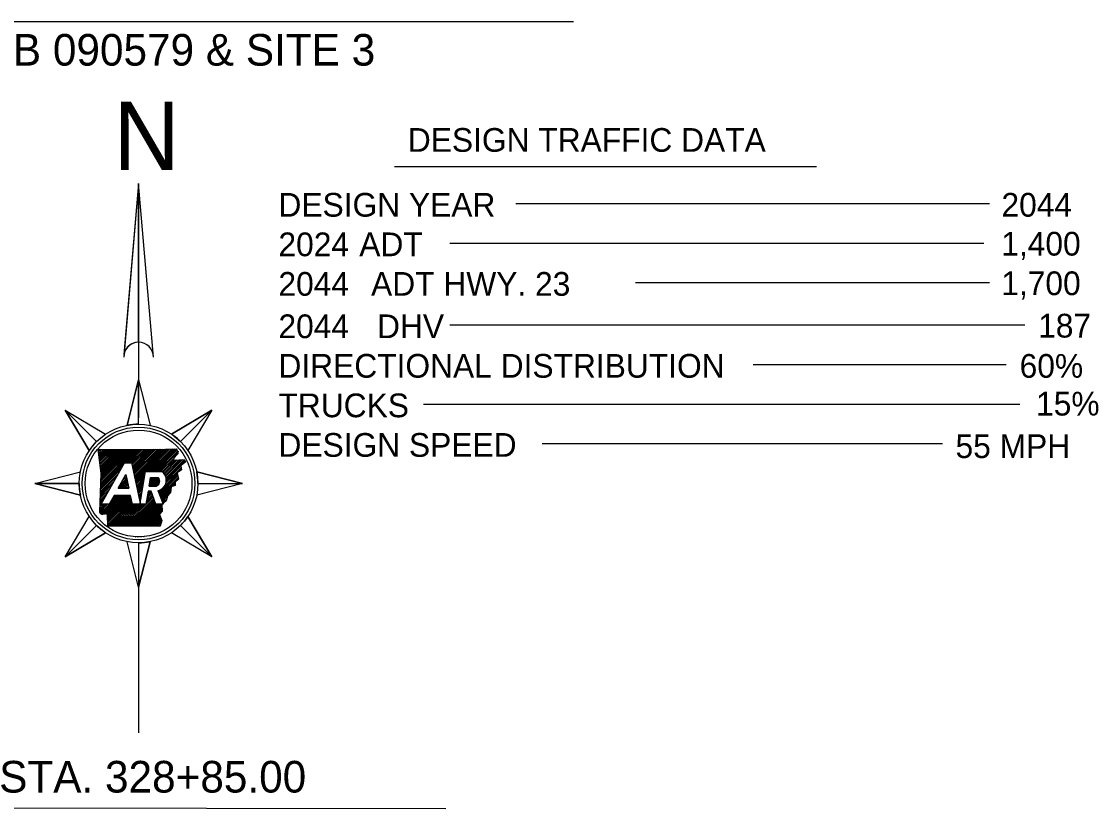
# Model space of a CAD drawing. Extents: x 0 to 3171, y 0 to 2059.
# Drawn here: x 2315 to 3132, y 658 to 1255 of the extents above; entities that cross this region are included whole.
import ezdxf

# ---------------------------------------------------------------- set-up
doc = ezdxf.new("R2010")
doc.units = 0
for name, color, linetype in [('Default', 7, 'Continuous'), ('R_Draft', 7, 'Continuous'), ('R_Water Annot', 7, 'Continuous')]:
    doc.layers.add(name, color=color, linetype=linetype)

msp = doc.modelspace()

# ---------------------------------------------------------------- linework, layer by layer
at = {"layer": 'Default'}
for p, q in [((2172.54, 1255.37), (2733.73, 1255.37)), ((2598, 1145.44), (2918, 1145.44)), ((2690.1, 1117.32), (3049.37, 1117.32)), ((2640.1, 1087.32), (3044.92, 1087.32)), ((2780.81, 1057.32), (3049.37, 1057.32)), ((2640.1, 1025.15), (3076.05, 1025.15)), ((2870.1, 995.15), (3061.97, 995.15)), ((2620.1, 965.15), (3072.35, 965.15)), ((2710.1, 935.15), (3013.64, 935.15))]:
    msp.add_line(p, q, dxfattribs=at)
msp.add_lwpolyline([(1931.87, 1191.31), (2273.76, 658.86), (2637.04, 658.32)], dxfattribs=at)
at = {"layer": 'R_Draft'}
for p, q in [((2404.02, 1132.45), (2392.93, 1002.73)), ((2404.02, 1132.45), (2404.02, 954.79)), ((2404.02, 1012.07), (2404.02, 1132.45)), ((2393.08, 1004.54), (2393.59, 1005.04)), ((2393.14, 1005.24), (2394.17, 1006.26)), ((2404.02, 983.63), (2395.25, 949.02)), ((2404.02, 949.88), (2404.02, 983.63)), ((2348.33, 960.56), (2372.2, 936.7)), ((2372.2, 936.7), (2348.33, 960.56)), ((2348.33, 960.56), (2366.61, 929.89)), ((2459.7, 960.56), (2429.03, 942.29)), ((2435.83, 936.7), (2459.7, 960.56)), ((2435.83, 936.7), (2459.7, 960.56)), ((2375.6, 889.12), (2393.35, 920.47)), ((2393.35, 920.47), (2398.63, 920.47)), ((2388.66, 901.42), (2394.46, 911.68)), ((2409.34, 913.93), (2421.67, 913.93)), ((2413.18, 909.51), (2418.97, 909.51)), ((2482.77, 904.88), (2448.15, 913.64)), ((2325.27, 904.88), (2359.02, 904.88)), ((2359.02, 904.88), (2325.27, 904.88)), ((2325.27, 904.88), (2359.88, 896.12)), ((2388.66, 901.42), (2396.66, 901.42)), ((2413.5, 899.09), (2411.36, 899.09)), ((2412.01, 902.81), (2417.3, 902.81)), ((2417.18, 889.12), (2413.5, 899.09)), ((2418.72, 899.62), (2422.6, 889.12)), ((2449.02, 904.88), (2482.77, 904.88)), ((2449.02, 904.88), (2482.77, 904.88)), ((2385.41, 895.7), (2381.69, 889.12)), ((2397.88, 895.7), (2385.41, 895.7)), ((2381.69, 889.12), (2375.6, 889.12)), ((2409.63, 889.12), (2399.29, 889.12)), ((2422.6, 889.12), (2417.18, 889.12)), ((2459.7, 849.2), (2441.42, 879.87)), ((2348.33, 849.2), (2372.2, 873.06)), ((2372.2, 873.06), (2348.33, 849.2)), ((2348.33, 849.2), (2379, 867.47)), ((2435.83, 873.06), (2459.7, 849.2)), ((2435.83, 873.06), (2459.7, 849.2)), ((2404.01, 859.88), (2404.02, 859.88)), ((2404.02, 826.13), (2412.78, 860.74)), ((2404.02, 859.88), (2404.02, 715.83)), ((2404.02, 859.88), (2404.02, 826.13))]:
    msp.add_line(p, q, dxfattribs=at)
for points in [[(2415.27, 1000.82), (2404.02, 1132.45), (2392.77, 1000.82)], [(2395.25, 949.02), (2404.02, 983.63), (2412.78, 949.02)], [(2366.61, 929.89), (2348.33, 960.56), (2379, 942.29)], [(2429.03, 942.29), (2459.7, 960.56), (2441.42, 929.89)], [(2373.29, 930.64), (2390.85, 930.63), (2406.26, 930.66), (2424.44, 930.94), (2432.87, 931.14)], [(2374.56, 883.13), (2375.54, 912.59), (2373.29, 930.64)], [(2438.38, 923.07), (2439.9, 921.48), (2436.11, 918.37), (2436.52, 915.23), (2433.27, 913.08), (2434.39, 908.25), (2431.88, 905.97), (2431.66, 903.48), (2428.61, 902.38), (2428.14, 897.7), (2425.95, 895.36), (2424.89, 891.83), (2421.71, 888.91), (2421.95, 883.76), (2419.78, 881.34), (2421.76, 876.92), (2420.39, 872.53)], [(2430.26, 922.66), (2438.5, 923.08)], [(2398.63, 920.47), (2405.16, 889.95), (2409.34, 913.93)], [(2359.88, 896.12), (2325.27, 904.88), (2359.88, 913.64)], [(2394.46, 911.68), (2396.66, 901.42)], [(2412.01, 902.81), (2413.18, 909.51)], [(2448.15, 913.64), (2482.77, 904.88), (2448.15, 896.12)], [(2411.36, 899.09), (2409.63, 889.12)], [(2399.29, 889.12), (2397.88, 895.7)], [(2379, 867.47), (2348.33, 849.2), (2366.61, 879.87)], [(2420.39, 872.53), (2380.59, 872.6), (2380.57, 881.38)], [(2441.42, 879.87), (2459.7, 849.2), (2429.03, 867.47)], [(2412.78, 860.74), (2404.02, 826.13), (2395.25, 860.74)]]:
    msp.add_lwpolyline(points, dxfattribs=at)
for radius in [45, 40.5]:
    msp.add_circle((2404.02, 904.88), radius, dxfattribs=at)
for centre, radius, start, end in [((2404.02, 1000.82), 11.25, 0, 180), ((2404.02, 1000.82), 11.25, 90, 170.22959), ((2404.02, 904.88), 45, 90, 101.22909), ((2404.02, 904.88), 45, 45, 56.22909), ((2404.02, 904.88), 45, 135, 146.22909), ((2416.03, 906.68), 4.07, 288.12683, 43.89016), ((2417.08, 907.42), 7.97, 281.86262, 54.87052), ((2404.02, 904.88), 45, 0, 11.22909), ((2404.02, 904.88), 45, 180, 191.22909), ((2404.02, 904.88), 45, 315, 326.22909), ((2404.02, 904.88), 45, 225, 236.22909), ((2404.02, 904.88), 45, 270, 281.22909)]:
    msp.add_arc(centre, radius, start, end, dxfattribs=at)
for points in [[(2432.87, 931.14), (2432.92, 930.66), (2433.07, 930.41), (2433.09, 929.96), (2433.28, 929.76), (2433.59, 929.57), (2433.88, 929.25), (2433.94, 928.88), (2433.85, 928.5), (2433.83, 928.08), (2433.79, 927.71), (2433.72, 927.37), (2433.46, 927.1), (2433.21, 926.9), (2432.99, 926.68), (2432.82, 926.44), (2432.54, 926.18), (2432.26, 925.91), (2432.03, 925.67), (2431.8, 925.36), (2431.69, 925.03), (2431.44, 924.79), (2431.25, 924.57), (2430.99, 924.28), (2430.86, 923.98), (2430.61, 923.65), (2430.55, 923.32), (2430.39, 923.06), (2430.38, 923.02)], [(2380.57, 881.38), (2380.61, 881.36), (2380.41, 881.5), (2380.12, 881.64), (2379.81, 881.66), (2379.41, 881.72), (2379.07, 881.75), (2378.72, 881.98), (2378.35, 881.74), (2377.94, 881.57), (2377.7, 881.76), (2377.39, 881.63), (2377.17, 881.7), (2376.79, 881.44), (2376.43, 881.53), (2376.17, 881.46), (2375.84, 881.47), (2375.78, 881.84), (2375.46, 881.89), (2375.19, 882.04), (2375.01, 882.43), (2374.88, 882.72), (2374.56, 883.13)]]:
    msp.add_spline(points, degree=3, dxfattribs=at)
at = {"layer": 'R_Water Annot'}
for p, q in [((2410.49, 913.93), (2427.57, 931.02)), ((2411.76, 913.93), (2428.88, 931.05)), ((2413.03, 913.93), (2430.18, 931.08)), ((2414.31, 913.93), (2431.48, 931.11)), ((2415.58, 913.93), (2432.78, 931.14)), ((2373.34, 930.24), (2373.74, 930.64)), ((2373.48, 929.11), (2375.01, 930.64)), ((2373.62, 927.98), (2376.28, 930.64)), ((2373.76, 926.85), (2377.55, 930.64)), ((2373.91, 925.72), (2378.83, 930.64)), ((2374.05, 924.58), (2380.1, 930.64)), ((2374.19, 923.45), (2381.37, 930.64)), ((2374.33, 922.32), (2382.64, 930.63)), ((2374.47, 921.19), (2383.91, 930.63)), ((2374.61, 920.06), (2385.19, 930.63)), ((2374.75, 918.93), (2386.46, 930.63)), ((2374.89, 917.79), (2387.73, 930.63)), ((2375.03, 916.66), (2389, 930.63)), ((2375.17, 915.53), (2390.27, 930.63)), ((2375.22, 902.84), (2403.03, 930.66)), ((2375.26, 904.16), (2401.75, 930.65)), ((2375.3, 905.48), (2400.48, 930.65)), ((2375.32, 914.4), (2391.55, 930.63)), ((2375.35, 906.79), (2399.2, 930.65)), ((2375.39, 908.11), (2397.93, 930.64)), ((2375.44, 909.43), (2396.65, 930.64)), ((2375.46, 913.27), (2392.82, 930.63)), ((2375.48, 910.74), (2395.38, 930.64)), ((2375.52, 912.06), (2394.1, 930.64)), ((2394.12, 920.47), (2404.3, 930.66)), ((2395.39, 920.47), (2405.58, 930.66)), ((2396.66, 920.47), (2406.86, 930.67)), ((2397.94, 920.47), (2408.16, 930.69)), ((2398.73, 919.99), (2409.45, 930.71)), ((2398.95, 918.94), (2410.74, 930.73)), ((2399.18, 917.9), (2412.03, 930.75)), ((2399.4, 916.85), (2413.33, 930.77)), ((2399.63, 915.8), (2414.62, 930.79)), ((2399.85, 914.75), (2415.91, 930.81)), ((2400.08, 913.7), (2417.21, 930.83)), ((2400.3, 912.65), (2418.5, 930.85)), ((2400.52, 911.6), (2419.79, 930.87)), ((2400.75, 910.56), (2421.08, 930.89)), ((2400.97, 909.51), (2422.38, 930.91)), ((2401.2, 908.46), (2423.67, 930.93)), ((2401.42, 907.41), (2424.97, 930.96)), ((2401.65, 906.36), (2426.27, 930.99)), ((2416.85, 913.93), (2433.07, 930.15)), ((2418.12, 913.93), (2433.68, 929.49)), ((2419.4, 913.93), (2433.85, 928.38)), ((2420.67, 913.93), (2430.94, 924.2)), ((2423.69, 911.86), (2434.72, 922.89)), ((2424.16, 911.06), (2436.06, 922.96)), ((2424.55, 910.18), (2437.4, 923.03)), ((2424.85, 909.2), (2438.61, 922.96)), ((2375.13, 900.21), (2390.69, 915.77)), ((2375.17, 901.53), (2392.35, 918.7)), ((2421.83, 913.82), (2430.69, 922.68)), ((2422.52, 913.24), (2432.03, 922.75)), ((2423.14, 912.59), (2433.38, 922.82)), ((2424.76, 905.29), (2436.31, 916.85)), ((2425.02, 908.1), (2439.2, 922.28)), ((2425.03, 906.83), (2436.17, 917.97)), ((2434.89, 914.15), (2436.46, 915.72)), ((2438.64, 920.45), (2439.8, 921.6)), ((2375, 896.26), (2385.7, 906.96)), ((2375.04, 897.58), (2387.36, 909.9)), ((2375.09, 898.89), (2389.02, 912.83)), ((2388.72, 901.42), (2395.26, 907.96)), ((2389.99, 901.42), (2395.48, 906.92)), ((2390.24, 904.22), (2395.03, 909.01)), ((2391.9, 907.15), (2394.81, 910.06)), ((2393.56, 910.08), (2394.59, 911.11)), ((2401.87, 905.31), (2409.09, 912.54)), ((2402.09, 904.27), (2408.82, 911)), ((2402.32, 903.22), (2408.56, 909.45)), ((2402.54, 902.17), (2408.29, 907.91)), ((2412.02, 902.81), (2418.72, 909.51)), ((2412.28, 904.34), (2417.44, 909.51)), ((2412.55, 905.88), (2416.17, 909.51)), ((2412.82, 907.43), (2414.9, 909.51)), ((2413.08, 908.97), (2413.62, 909.51)), ((2413.29, 902.81), (2419.42, 908.94)), ((2414.56, 902.81), (2419.85, 908.1)), ((2415.84, 902.81), (2420.09, 907.06)), ((2419.51, 897.49), (2433.62, 911.6)), ((2419.85, 896.56), (2433.85, 910.57)), ((2420.19, 895.63), (2434.09, 909.53)), ((2420.54, 894.71), (2434.33, 908.5)), ((2423.65, 902.91), (2433.38, 912.64)), ((2374.91, 893.63), (2382.38, 901.1)), ((2374.95, 894.95), (2384.04, 904.03)), ((2391.26, 901.42), (2395.71, 905.87)), ((2392.54, 901.42), (2395.93, 904.82)), ((2393.81, 901.42), (2396.16, 903.77)), ((2395.08, 901.42), (2396.38, 902.72)), ((2396.35, 901.42), (2396.6, 901.67)), ((2402.77, 901.12), (2408.02, 906.37)), ((2402.99, 900.07), (2407.75, 904.83)), ((2403.22, 899.02), (2407.48, 903.29)), ((2403.44, 897.98), (2407.21, 901.75)), ((2403.66, 896.93), (2406.94, 900.21)), ((2403.89, 895.88), (2406.67, 898.66)), ((2410.92, 896.54), (2413.46, 899.09)), ((2411.19, 898.09), (2412.19, 899.09)), ((2417.11, 902.81), (2419.98, 905.68)), ((2418.82, 899.35), (2419.21, 899.74)), ((2419.16, 898.42), (2421.58, 900.85)), ((2420.88, 893.78), (2428.51, 901.41)), ((2421.22, 892.85), (2428.37, 900)), ((2421.57, 891.92), (2428.23, 898.58)), ((2429.98, 902.88), (2431.76, 904.66)), ((2374.78, 889.68), (2377.39, 892.29)), ((2374.82, 891), (2379.06, 895.23)), ((2374.87, 892.31), (2380.72, 898.16)), ((2375.06, 882.32), (2388.43, 895.7)), ((2375.81, 881.8), (2389.71, 895.7)), ((2376.73, 881.44), (2390.98, 895.7)), ((2378.24, 881.68), (2392.25, 895.7)), ((2379.53, 881.7), (2393.52, 895.7)), ((2380.53, 881.43), (2394.8, 895.7)), ((2380.57, 878.93), (2397.34, 895.7)), ((2380.57, 880.2), (2396.07, 895.7)), ((2380.58, 877.66), (2398.01, 895.09)), ((2380.58, 876.39), (2398.24, 894.04)), ((2380.58, 875.12), (2398.46, 893)), ((2380.59, 873.85), (2398.69, 891.95)), ((2380.61, 872.6), (2398.91, 890.9)), ((2383.13, 891.67), (2387.16, 895.7)), ((2384.79, 894.6), (2385.89, 895.7)), ((2393.32, 872.58), (2415.21, 894.47)), ((2394.59, 872.57), (2415.55, 893.54)), ((2395.86, 872.57), (2415.89, 892.61)), ((2397.13, 872.57), (2416.24, 891.68)), ((2398.4, 872.57), (2416.58, 890.75)), ((2404.11, 894.83), (2406.41, 897.12)), ((2404.34, 893.78), (2406.14, 895.58)), ((2404.56, 892.73), (2405.87, 894.04)), ((2404.79, 891.68), (2405.6, 892.5)), ((2405.01, 890.64), (2405.33, 890.96)), ((2409.85, 890.38), (2414.86, 895.4)), ((2410.11, 891.92), (2414.52, 896.33)), ((2410.38, 893.46), (2414.18, 897.26)), ((2410.65, 895), (2413.83, 898.19)), ((2421.91, 890.99), (2425.81, 894.89)), ((2422.25, 890.06), (2425.27, 893.07)), ((2374.58, 883.12), (2380.58, 889.12)), ((2374.61, 884.41), (2379.31, 889.12)), ((2374.65, 885.73), (2378.04, 889.12)), ((2374.69, 887.05), (2376.76, 889.12)), ((2374.74, 888.36), (2375.73, 889.36)), ((2381.88, 872.6), (2399.13, 889.85)), ((2383.15, 872.59), (2399.67, 889.12)), ((2384.42, 872.59), (2400.95, 889.12)), ((2385.69, 872.59), (2402.22, 889.12)), ((2386.96, 872.59), (2403.49, 889.12)), ((2388.23, 872.58), (2404.76, 889.12)), ((2389.5, 872.58), (2406.04, 889.12)), ((2390.77, 872.58), (2407.31, 889.12)), ((2392.04, 872.58), (2408.58, 889.12)), ((2399.67, 872.57), (2416.92, 889.82)), ((2400.94, 872.56), (2417.49, 889.12)), ((2402.21, 872.56), (2418.76, 889.12)), ((2403.48, 872.56), (2420.04, 889.12)), ((2404.75, 872.56), (2421.31, 889.12)), ((2406.02, 872.56), (2421.74, 888.27)), ((2407.29, 872.55), (2421.79, 887.05)), ((2408.56, 872.55), (2421.85, 885.84)), ((2409.83, 872.55), (2421.91, 884.62)), ((2411.11, 872.55), (2419.82, 881.26)), ((2412.38, 872.55), (2420.21, 880.38)), ((2413.65, 872.54), (2420.6, 879.5)), ((2414.92, 872.54), (2421, 878.62)), ((2416.19, 872.54), (2421.39, 877.74)), ((2417.46, 872.54), (2421.72, 876.8)), ((2418.73, 872.53), (2421.14, 874.95)), ((2420, 872.53), (2420.57, 873.1))]:
    msp.add_line(p, q, dxfattribs=at)
msp.add_circle((2404.02, 904.88), 42.75, dxfattribs=at)

# ---------------------------------------------------------------- texts
at = {"layer": 'Default'}
for s, height, p in [('END JOB 090579 & SITE 3 ', 24, (2191.03, 1221.92)), ('DESIGN TRAFFIC DATA', 18, (2608.2, 1156.54)), ('DESIGN YEAR', 18, (2510.1, 1107.32)), ('2044', 18, (3058.4, 1107.32)), ('2024', 18, (2510.1, 1077.32)), (' ADT', 18, (2564.7, 1077.32)), ('1,400', 18, (3058.24, 1077.79)), ('2044', 18, (2510.1, 1047.32)), (' ADT HWY. 23 ', 18, (2573.65, 1047.32)), ('1,700', 18, (3058.24, 1047.79)), ('2044', 18, (2510.1, 1015.15)), ('DHV', 18, (2584.85, 1015.15)), ('187', 18, (3086.19, 1015.61)), ('DIRECTIONAL DISTRIBUTION', 18, (2510.1, 985.15)), ('60%', 18, (3072.15, 985.1)), ('TRUCKS', 18, (2510.1, 955.15)), ('15%', 18, (3084.63, 956.44)), ('DESIGN SPEED', 18, (2510.1, 925.15)), ('55 MPH', 18, (3023.54, 924.2)), ('STA. 328+85.00', 24, (2298.31, 670.4))]:
    msp.add_text(s, height=height, dxfattribs=at).set_placement(p)
at = {"layer": 'R_Draft'}
for s, height, p in [('N', 51.92, (2385.04, 1142.66)), ('DWB 7-27-17', 0.875, (2401.26, 863.63))]:
    msp.add_text(s, height=height, dxfattribs=at).set_placement(p)

doc.saveas('drawing.dxf')
